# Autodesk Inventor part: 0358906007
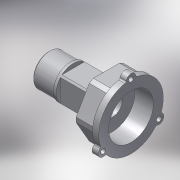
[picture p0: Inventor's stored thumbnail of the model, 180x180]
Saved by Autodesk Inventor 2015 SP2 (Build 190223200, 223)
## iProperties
Created: 2017-01
Part Number: 0358906007
Material: PVC-Piping
Description: PLASSON MALE BSPT WITH FREE NUT 3/4"-1"
Document SubType Name: Modeling
Designer: KIM
Mass: 43.954 g
Surface Area: 139.205 cm^2
Volume: 31.3957 cm^3
Density: 1.4 g/cm^3
Appearance: Smooth - White
Author: KIM
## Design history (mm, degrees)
derived "03589.ipt"
feature "Solid1::03589.ipt"
tag "TaggingFeature1"
body "Solid1"
other parameters: "d0" = 61, "d1" = 33.249, "d2" = 24.117, "d4" = 25.32285, "d5" = 48, "d6" = 18.3, "d7" = 4.575, "d8" = 47.04, "d9" = 4.575, "d10" = 14.4702, "d13" = 1, "d14" = 2, "d15" = 9.5, "d17" = 0, "d19" = 360 deg, "d21" = 6.02925, "d22" = 45 deg, "d30" = 0, "d31" = 2, "d34" = 7.2351, "d36" = 0, "d37" = 3.61755, "d39" = 0, "d41" = 360 deg, "d43" = 1.20585, "d44" = 0.72351, "d47" = 16, "G_" = 33.249, "G_1" = 24.117, "E_" = 48, "H_" = 61, "l_2" = 16
